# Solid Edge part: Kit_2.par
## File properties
Author: ahadarics
Last saved by: ahadarics
Revision: 77
Sűrűség: 0,000 kg/m^3
Pontosság: 0,990
Username: ahadarics
Dokumentum tartalom típus: 0
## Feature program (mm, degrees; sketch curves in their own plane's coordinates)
base feature "unnamed BaseFeature 1"
sketch for "Furat_1" plane through (0, -0.5, 8.5) normal (0, 0, 1) x-axis (0, 1, 0)
hole "Furat_1" diameter 5 finite  ThreadDepth = 4.5 mm
chamfer "Letörés_1" setback 0.5
sketch for "unnamed Protrusion 1" #1 plane through (0, 22, 0) normal (0, 1, 0) x-axis (0, 0, -1)
  line (-5.2915, -6) -> (5.2915, -6)
  arc centre (0, 0) radius 8 from (5.2915, -6) to (-5.2915, -6) cw
sketch for "unnamed Protrusion 1" #2 plane through (0, 22, 0) normal (0, 1, 0) x-axis (0, 0, -1)
  line (-5.2915, 6) -> (5.2915, 6)
extrude "unnamed Protrusion 1" add to key point along -normal
thread "unnamed Thread 1"
chamfer "Letörés_2" setback 1
sketch for "Kivágás_1" #1 plane through (0, 22, 0) normal (0, 1, 0) x-axis (0, 0, -1)
  line (-5.2915, -6) -> (5.2915, -6)
  arc centre (0, 0) radius 8 from (5.2915, -6) to (-5.2915, -6) cw
sketch for "Kivágás_1" #2 plane through (0, 22, 0) normal (0, 1, 0) x-axis (0, 0, -1)
  line (-5.2915, 6) -> (5.2915, 6)
extrude "Kivágás_1" cut finite 16 along -normal
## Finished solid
Body 1: solid body, 33 faces, 74 edges, 42 vertices.
  Faces by surface: plane 14, cylinder 11, cone 8
  Edges by curve: line 34, circle 32, intersection 4, spline 4
Bounding box of the edges (mm): 19.000 x 28.500 x 18.100, from (-9.5, -6.5, -9.5) to (9.5, 22, 8.6).
Cylindrical faces by radius (mm): R2.06 x1, R2.067 x1, R3 x1, R6.85 x2, R8 x4, R8.6 x1, R9.5 x1
Conical faces (half-angle, radius in mm at the cone's reference point): 45 deg R2.567 x1, 45 deg R3.1 x2, 45 deg R8 x2, 59 deg R1.0335 x1, 60 deg R7.425 x2
Planar faces by outward normal: +x 1, +y 8, +z 2, -x 1, -y 2
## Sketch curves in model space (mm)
arc centre (0, 22, 0) radius 8 from (6, 22, -5.2915) through (7.9967, 22, 0.2312) to (6, 22, 5.2915)
line (6, 22, 5.2915) -> (6, 22, -5.2915)
arc centre (0, 22, 0) radius 8 from (-6, 22, 5.2915) through (-7.9967, 22, -0.2312) to (-6, 22, -5.2915)
line (-6, 22, 5.2915) -> (-6, 22, -5.2915)
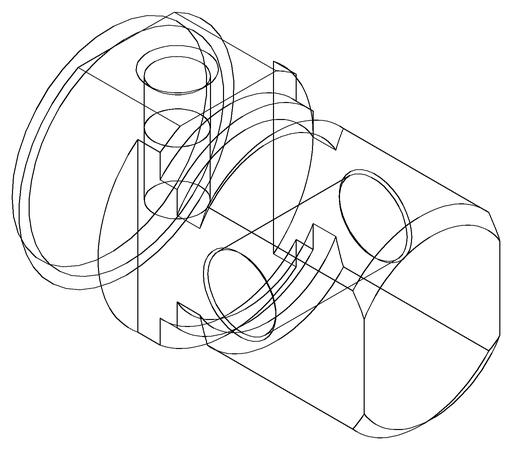
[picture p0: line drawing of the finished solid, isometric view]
